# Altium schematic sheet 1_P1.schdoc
size 429 x 518 mm; Symbol: Sheet-Symbol_A4; Device: Sheet-Symbol_A4; Company: 嘉立创EDA; Drawed: Solituder; Version: V8.0; Page Size: A4; @Project Name: FOC12; @Page Count: 1; @Update Date: 2025-05-16; @Create Date: 2024-12-24; @Schematic Name: Schematic1; @Page No: 1; @Page Name: P1; @Board Name: 驱动板; @Create Time: 09:30:22; @Update Time: 20:05:17; Width: 1655; Height: 2000; Region Start: 1; X Region Count: 6; Y Region Count: 4; Blade Width: 10; Title Block Position: 3
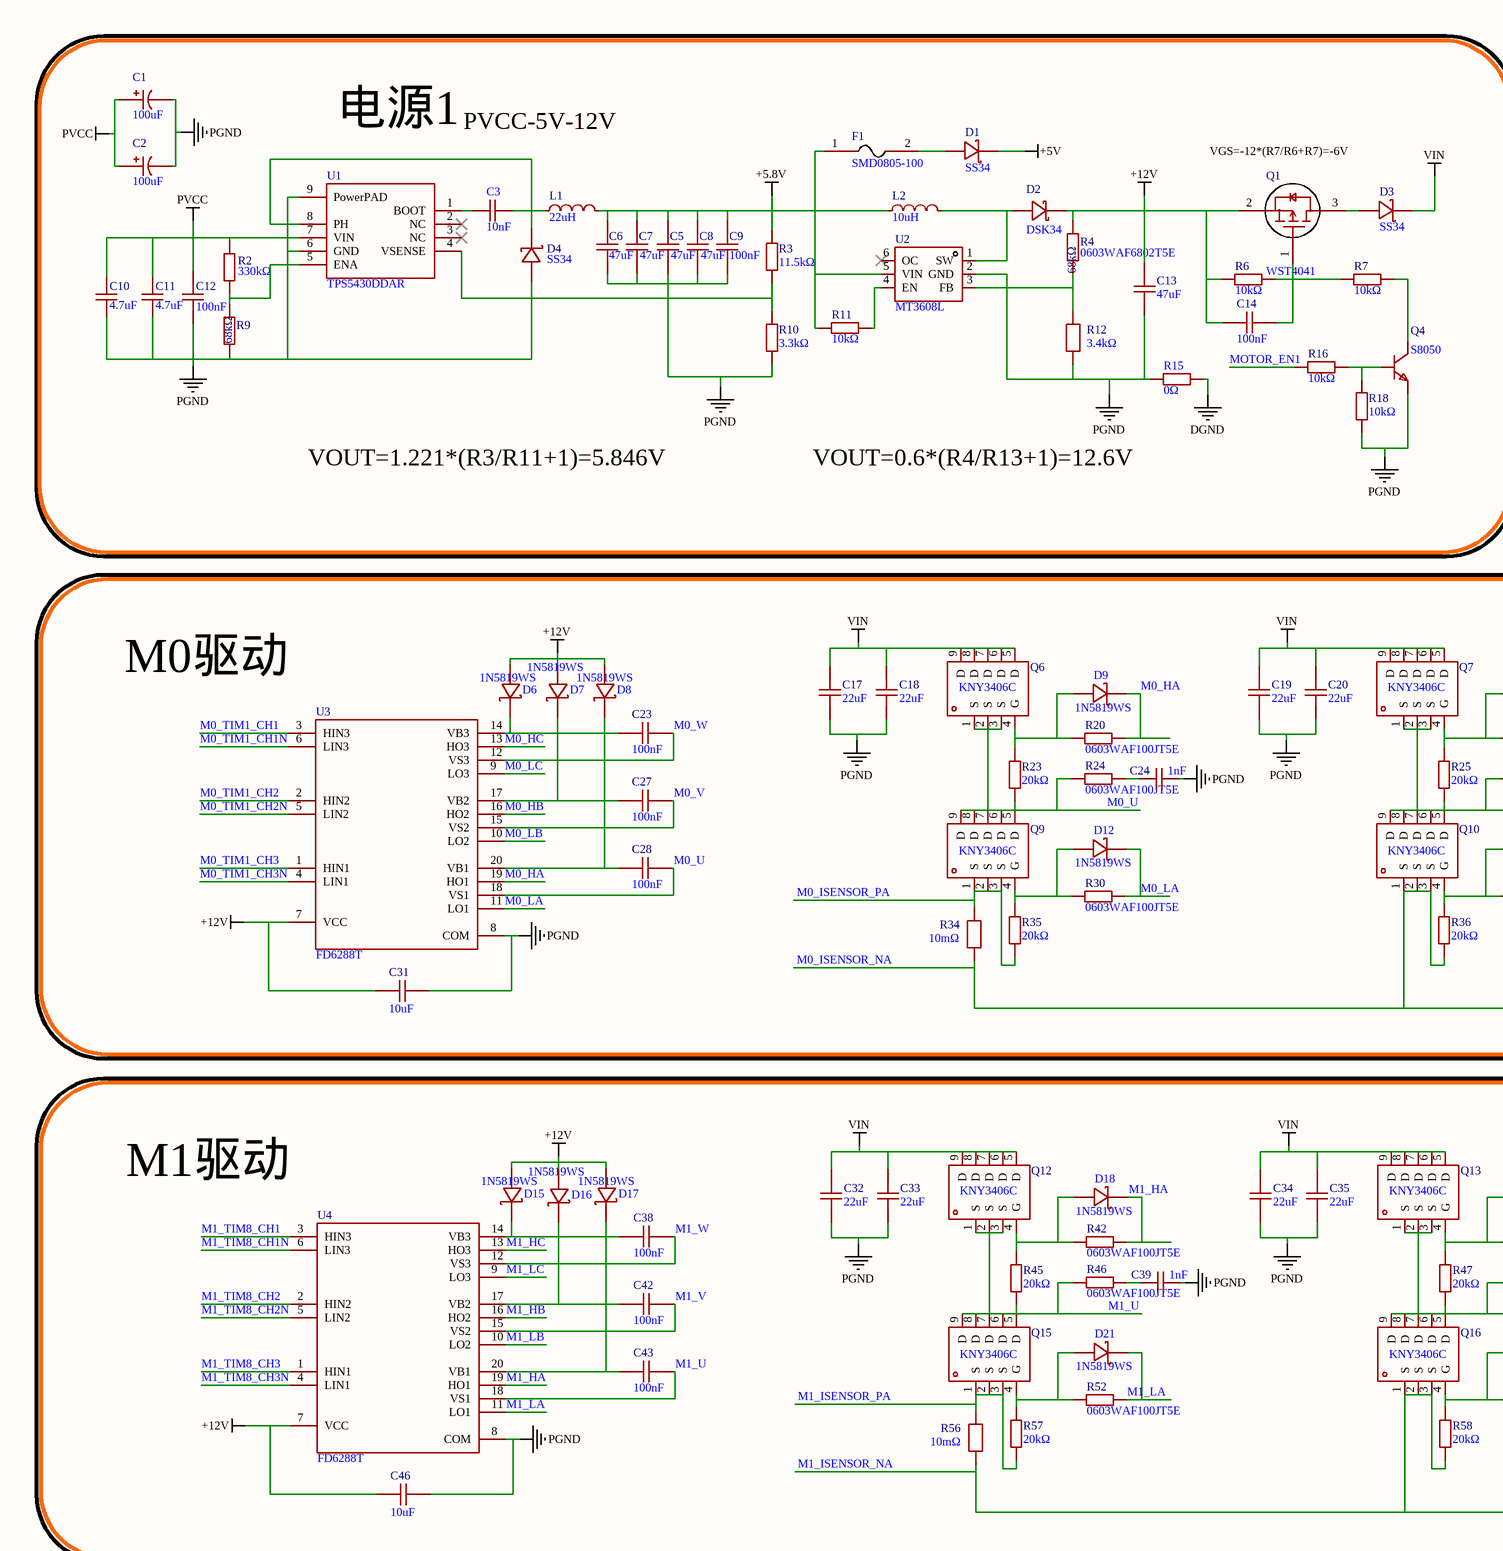
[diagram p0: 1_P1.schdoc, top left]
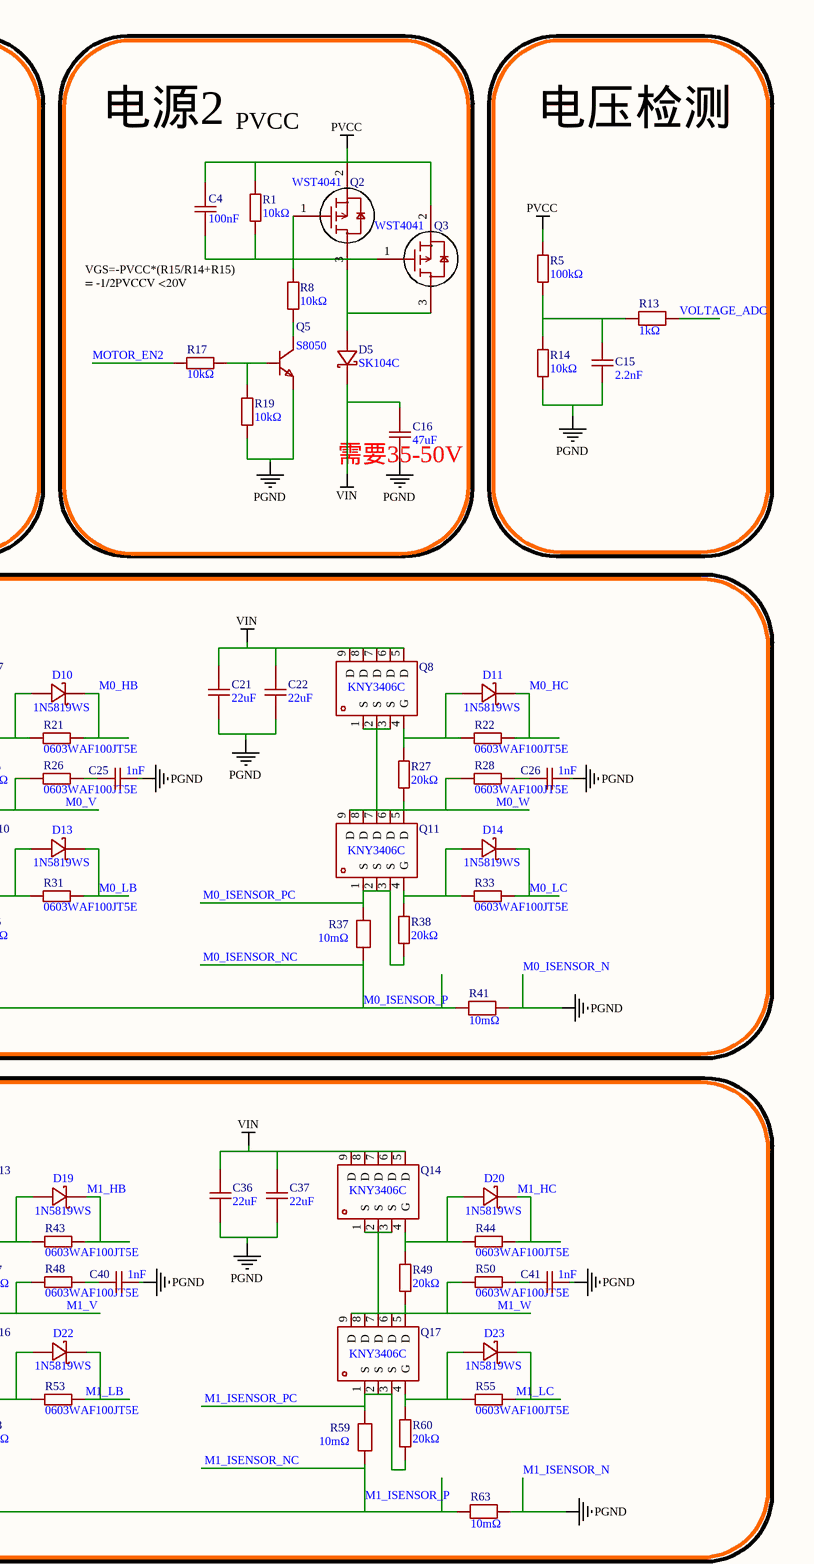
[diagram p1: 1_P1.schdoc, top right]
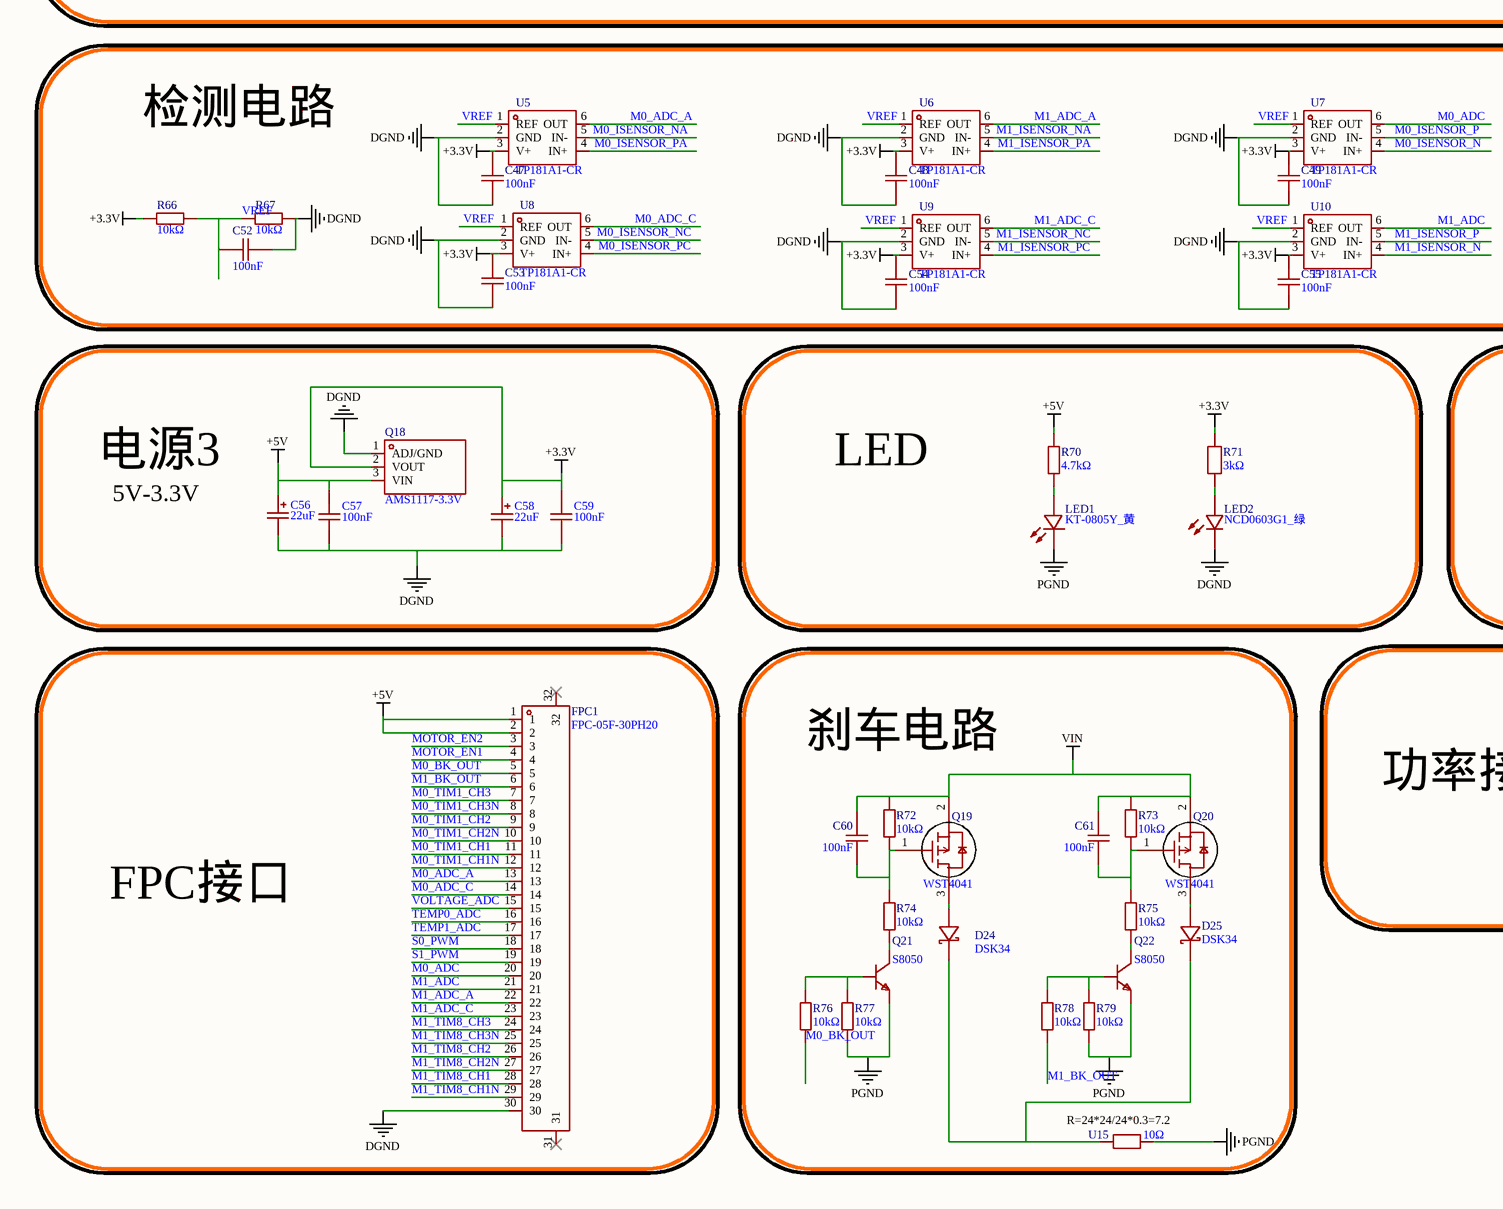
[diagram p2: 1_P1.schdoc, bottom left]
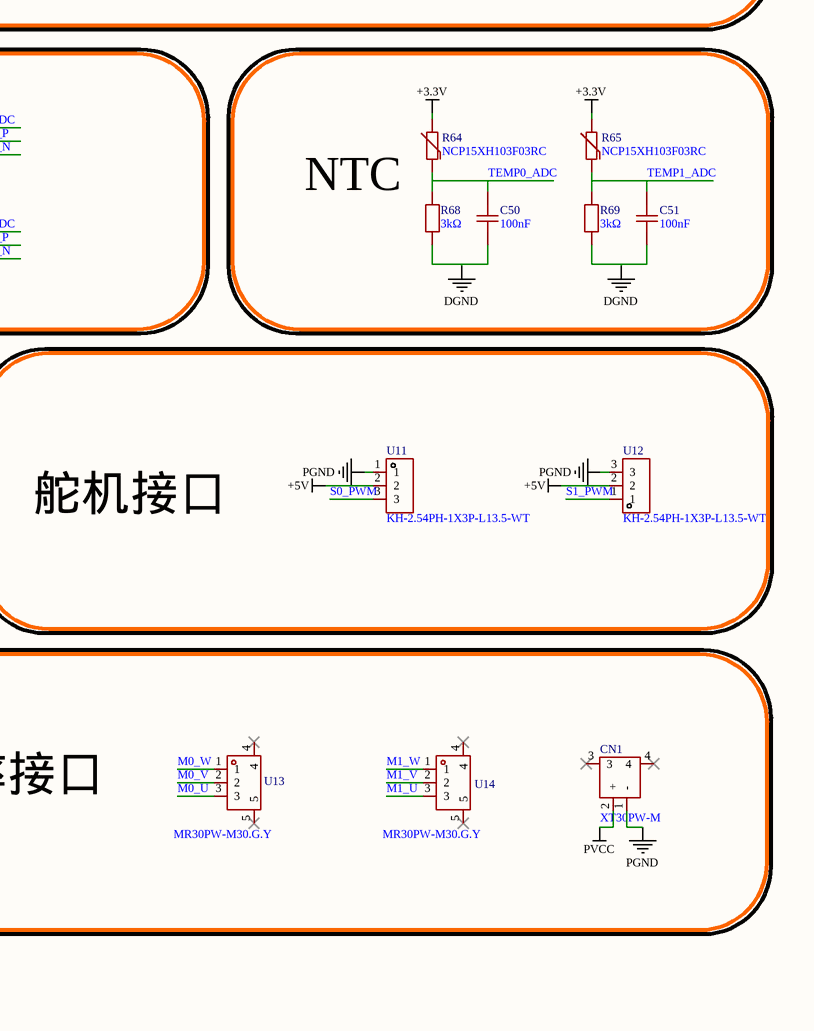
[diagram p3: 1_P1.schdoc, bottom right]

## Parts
C1  100uF  [CAP-SMD_BD10.0-L10.3-W10.3-FD]
C2  100uF  [CAP-SMD_BD10.0-L10.3-W10.3-FD]
C3  10nF  [C0603]
C4  100nF  [C0603]
C5  47uF  [C1206]
C6  47uF  [C1206]
C7  47uF  [C1206]
C8  47uF  [C1206]
C9  100nF  [C0603]
C10  4.7uF  [C0805]
C11  4.7uF  [C0805]
C12  100nF  [C0603]
C13  47uF  [C1206]
C14  100nF  [C0603]
C15  2.2nF  [C0402]
C16  47uF  [C1206]
C17  22uF  [C1206]
C18  22uF  [C1206]
C19  22uF  [C1206]
C20  22uF  [C1206]
C21  22uF  [C1206]
C22  22uF  [C1206]
C23  100nF  [C0603]
C24  1nF  [C0402]
C25  1nF  [C0402]
C26  1nF  [C0402]
C27  100nF  [C0603]
C28  100nF  [C0603]
C31  10uF  [C0805]
C32  22uF  [C1206]
C33  22uF  [C1206]
C34  22uF  [C1206]
C35  22uF  [C1206]
C36  22uF  [C1206]
C37  22uF  [C1206]
C38  100nF  [C0603]
C39  1nF  [C0402]
C40  1nF  [C0402]
C41  1nF  [C0402]
C42  100nF  [C0603]
C43  100nF  [C0603]
C46  10uF  [C0805]
C47  100nF  [C0402]
C48  100nF  [C0402]
C49  100nF  [C0402]
C50  100nF  [C0603]
C51  100nF  [C0603]
C52  100nF  [C0402]
C53  100nF  [C0402]
C54  100nF  [C0402]
C55  100nF  [C0402]
C56  22uF  [CASE-A_3216]
C57  100nF  [C0603]
C58  22uF  [CASE-A_3216]
C59  100nF  [C0603]
C60  100nF  [C0603]
C61  100nF  [C0603]
CN1  XT30PW-M  [CONN-TH_XT30PW-M]
D1  SS34  [SMA_L4.3-W2.6-LS5.2-RD]
D2  DSK34  [SOD-123FL_L2.7-W1.8-LS3.8-RD]
D3  SS34  [SMA_L4.3-W2.6-LS5.2-RD]
D4  SS34  [SMA_L4.3-W2.6-LS5.2-RD]
D5  SK104C  [SMC_L6.9-W5.9-LS7.9-RD]
D6  1N5819WS  [SOD-323_L1.8-W1.3-LS2.5-RD]
D7  1N5819WS  [SOD-323_L1.8-W1.3-LS2.5-RD]
D8  1N5819WS  [SOD-323_L1.8-W1.3-LS2.5-RD]
D9  1N5819WS  [SOD-323_L1.8-W1.3-LS2.5-RD]
D10  1N5819WS  [SOD-323_L1.8-W1.3-LS2.5-RD]
D11  1N5819WS  [SOD-323_L1.8-W1.3-LS2.5-RD]
D12  1N5819WS  [SOD-323_L1.8-W1.3-LS2.5-RD]
D13  1N5819WS  [SOD-323_L1.8-W1.3-LS2.5-RD]
D14  1N5819WS  [SOD-323_L1.8-W1.3-LS2.5-RD]
D15  1N5819WS  [SOD-323_L1.8-W1.3-LS2.5-RD]
D16  1N5819WS  [SOD-323_L1.8-W1.3-LS2.5-RD]
D17  1N5819WS  [SOD-323_L1.8-W1.3-LS2.5-RD]
D18  1N5819WS  [SOD-323_L1.8-W1.3-LS2.5-RD]
D19  1N5819WS  [SOD-323_L1.8-W1.3-LS2.5-RD]
D20  1N5819WS  [SOD-323_L1.8-W1.3-LS2.5-RD]
D21  1N5819WS  [SOD-323_L1.8-W1.3-LS2.5-RD]
D22  1N5819WS  [SOD-323_L1.8-W1.3-LS2.5-RD]
D23  1N5819WS  [SOD-323_L1.8-W1.3-LS2.5-RD]
D24  DSK34  [SOD-123FL_L2.7-W1.8-LS3.8-RD]
D25  DSK34  [SOD-123FL_L2.7-W1.8-LS3.8-RD]
F1  SMD0805-100  [F0805]
FPC1  FPC-05F-30PH20  [FPC-SMD_30P-P0.50_XUNPU_FPC-05F-30PH20]
L1  22uH  [IND-SMD_L7.3-W6.6_MHCI06030]
L2  10uH  [IND-SMD_L5.4-W5.2_FXL0530]
LED1  KT-0805Y_黄  [LED0805-R-RD]
LED2  NCD0603G1_绿  [LED0603-RD_1]
Q1  WST4041  [SOT-23_L2.9-W1.3-P1.90-LS2.4-BR]
Q2  WST4041  [SOT-23_L2.9-W1.3-P1.90-LS2.4-BR]
Q3  WST4041  [SOT-23_L2.9-W1.3-P1.90-LS2.4-BR]
Q4  S8050  [SOT-23-3_L2.9-W1.3-P1.90-LS2.4-BR]
Q5  S8050  [SOT-23-3_L2.9-W1.3-P1.90-LS2.4-BR]
Q6  KNY3406C  [PDFN-8_L4.9-W5.8-P1.27-LS6.1-BL]
Q7  KNY3406C  [PDFN-8_L4.9-W5.8-P1.27-LS6.1-BL]
Q8  KNY3406C  [PDFN-8_L4.9-W5.8-P1.27-LS6.1-BL]
Q9  KNY3406C  [PDFN-8_L4.9-W5.8-P1.27-LS6.1-BL]
Q10  KNY3406C  [PDFN-8_L4.9-W5.8-P1.27-LS6.1-BL]
Q11  KNY3406C  [PDFN-8_L4.9-W5.8-P1.27-LS6.1-BL]
Q12  KNY3406C  [PDFN-8_L4.9-W5.8-P1.27-LS6.1-BL]
Q13  KNY3406C  [PDFN-8_L4.9-W5.8-P1.27-LS6.1-BL]
Q14  KNY3406C  [PDFN-8_L4.9-W5.8-P1.27-LS6.1-BL]
Q15  KNY3406C  [PDFN-8_L4.9-W5.8-P1.27-LS6.1-BL]
Q16  KNY3406C  [PDFN-8_L4.9-W5.8-P1.27-LS6.1-BL]
Q17  KNY3406C  [PDFN-8_L4.9-W5.8-P1.27-LS6.1-BL]
Q18  AMS1117-3.3V  [SOT-89-3_L4.5-W2.5-P1.50-LS4.2-BR]
Q19  WST4041  [SOT-23_L2.9-W1.3-P1.90-LS2.4-BR]
Q20  WST4041  [SOT-23_L2.9-W1.3-P1.90-LS2.4-BR]
Q21  S8050  [SOT-23-3_L2.9-W1.3-P1.90-LS2.4-BR]
Q22  S8050  [SOT-23-3_L2.9-W1.3-P1.90-LS2.4-BR]
R1  10kΩ  [R0402]
R2  330kΩ  [R0603]
R3  11.5kΩ  [R0402]
R4  0603WAF6802T5E  value 68kΩ  [R0603]
R5  100kΩ  [R0402]
R6  10kΩ  [R0402]
R7  10kΩ  [R0402]
R8  10kΩ  [R0402]
R9  value 68kΩ  [R0603]  (hidden comment: 0603WAF6802T5E)
R10  3.3kΩ  [R0402]
R11  10kΩ  [R0402]
R12  3.4kΩ  [R0603]
R13  1kΩ  [R0402]
R14  10kΩ  [R0402]
R15  0Ω  [R0603]
R16  10kΩ  [R0402]
R17  10kΩ  [R0402]
R18  10kΩ  [R0402]
R19  10kΩ  [R0402]
R20  0603WAF100JT5E  [R0603]
R21  0603WAF100JT5E  [R0603]
R22  0603WAF100JT5E  [R0603]
R23  20kΩ  [R0402]
R24  0603WAF100JT5E  [R0603]
R25  20kΩ  [R0402]
R26  0603WAF100JT5E  [R0603]
R27  20kΩ  [R0402]
R28  0603WAF100JT5E  [R0603]
R30  0603WAF100JT5E  [R0603]
R31  0603WAF100JT5E  [R0603]
R33  0603WAF100JT5E  [R0603]
R34  10mΩ  [R2512]
R35  20kΩ  [R0402]
R36  20kΩ  [R0402]
R37  10mΩ  [R2512]
R38  20kΩ  [R0402]
R41  10mΩ  [R2512]
R42  0603WAF100JT5E  [R0603]
R43  0603WAF100JT5E  [R0603]
R44  0603WAF100JT5E  [R0603]
R45  20kΩ  [R0402]
R46  0603WAF100JT5E  [R0603]
R47  20kΩ  [R0402]
R48  0603WAF100JT5E  [R0603]
R49  20kΩ  [R0402]
R50  0603WAF100JT5E  [R0603]
R52  0603WAF100JT5E  [R0603]
R53  0603WAF100JT5E  [R0603]
R55  0603WAF100JT5E  [R0603]
R56  10mΩ  [R2512]
R57  20kΩ  [R0402]
R58  20kΩ  [R0402]
R59  10mΩ  [R2512]
R60  20kΩ  [R0402]
R63  10mΩ  [R2512]
R64  NCP15XH103F03RC  [R0402]
R65  NCP15XH103F03RC  [R0402]
R66  10kΩ  [R0402]
R67  10kΩ  [R0402]
R68  3kΩ  [R0402]
R69  3kΩ  [R0402]
R70  4.7kΩ  [R0402]
R71  3kΩ  [R0402]
R72  10kΩ  [R0402]
R73  10kΩ  [R0402]
R74  10kΩ  [R0402]
R75  10kΩ  [R0402]
R76  10kΩ  [R0402]
R77  10kΩ  [R0402]
R78  10kΩ  [R0402]
R79  10kΩ  [R0402]
U1  TPS5430DDAR  [ESOP-8_L4.9-W3.9-P1.27-LS6.0-TL-EP]
U2  MT3608L  [SOT-23-6_L2.9-W1.6-P0.95-LS2.8-BL_3]
U3  FD6288T  [TSSOP-20_L6.5-W4.4-P0.65-LS6.4-BL]
U4  FD6288T  [TSSOP-20_L6.5-W4.4-P0.65-LS6.4-BL]
U5  TP181A1-CR  [SC70-6_L2.1-W1.3-P0.65-LS2.3-BL]
U6  TP181A1-CR  [SC70-6_L2.1-W1.3-P0.65-LS2.3-BL]
U7  TP181A1-CR  [SC70-6_L2.1-W1.3-P0.65-LS2.3-BL]
U8  TP181A1-CR  [SC70-6_L2.1-W1.3-P0.65-LS2.3-BL]
U9  TP181A1-CR  [SC70-6_L2.1-W1.3-P0.65-LS2.3-BL]
U10  TP181A1-CR  [SC70-6_L2.1-W1.3-P0.65-LS2.3-BL]
U11  KH-2.54PH-1X3P-L13.5-WT  [HDR-SMD_3P-P2.54-H-M_KH-2.54PH-1X3P-L13.5-WT]
U12  KH-2.54PH-1X3P-L13.5-WT  [HDR-SMD_3P-P2.54-H-M_KH-2.54PH-1X3P-L13.5-WT]
U13  MR30PW-M30.G.Y  [CONN-TH_MR30PW-M30-G-Y]
U14  MR30PW-M30.G.Y  [CONN-TH_MR30PW-M30-G-Y]
U15  10Ω  [TO-220-2_L10.1-W4.5-P5.08-L]

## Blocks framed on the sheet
电源1: C1-C3 C5-C14 D1-D4 F1 L1 L2 Q1 Q4 R2-R4 R6 R7 R9-R12 R15 R16 R18 U1 U2
电源2: C4 C16 D5 Q2 Q3 Q5 R1 R8 R17 R19
电压检测: C15 R5 R13 R14
M0驱动: C17-C28 C31 D6-D14 Q6-Q11 R20-R28 R30 R31 R33-R38 R41 U3
M1驱动: C32-C43 C46 D15-D23 Q12-Q17 R42-R50 R52 R53 R55-R60 R63 U4
检测电路: C47-C49 C52-C55 R66 R67 U5-U10
NTC: C50 C51 R64 R65 R68 R69
电源3: C56-C59 Q18
LED: LED1 LED2 R70 R71
舵机接口: U11 U12
FPC接口: FPC1
刹车电路: C60 C61 D24 D25 Q19-Q22 R72-R79 U15
功率接口: CN1 U13 U14

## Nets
+3.3V: C47.2 C48.2 C49.2 C53.2 C54.2 C55.2 C58.1 C59.2 Q18.2(VOUT) R64.2 R65.2 R66.1 R71.2 U5.3(V+) U6.3(V+) U7.3(V+) U8.3(V+) U9.3(V+) U10.3(V+)
+5.8V: C5.2 C6.2 C7.2 C8.2 C9.1 F1.1 L1.2 L2.1 R3.2 R11.2 U2.5(VIN)
+5V: C56.1 C57.2 D1.1(K) FPC1.1 FPC1.2 Q18.3(VIN) R70.2 U11.2 U12.2
+12V: C13.2 C14.2 C31.2 C46.2 D2.1(K) D6.2(A) D7.2(A) D8.2(A) D15.2(A) D16.2(A) D17.2(A) Q1.2(S) R4.2 R6.2 U3.7(VCC) U4.7(VCC)
DGND: C47.1 C48.1 C49.1 C50.1 C51.1 C52.1 C53.1 C54.1 C55.1 C56.2 C57.1 C58.2 C59.1 FPC1.30 LED2.1(K) Q18.1(ADJ/GND) R15.1 R67.2 R68.1 R69.1 U5.2(GND) U6.2(GND) U7.2(GND) U8.2(GND) U9.2(GND) U10.2(GND)
M0_ISENSOR_N: C1.2 C2.2 C5.1 C6.1 C7.1 C8.1 C9.2 C10.1 C11.1 C12.1 C13.1 C15.1 C16.1 C17.1 C18.1 C19.1 C20.1 C21.1 C22.1 C24.2 C25.2 C26.2 C31.1 C32.1 C33.1 C34.1 C35.1 C36.1 C37.1 C39.2 C40.2 C41.2 C46.1 CN1.1(-) D4.2(A) LED1.2(-) Q4.2(E) Q5.2(E) Q21.2(E) Q22.2(E) R9.1 R10.1 R12.1 R14.2 R15.2 R18.2 R19.2 R41.1 R63.1 R77.2 R79.2 U1.6(GND) U1.9(PowerPAD) U2.2(GND) U3.8(COM) U4.8(COM) U7.4(IN+) U10.4(IN+) U11.1 U12.3 U15.2  [also labelled M1_ISENSOR_N, PGND]
PVCC: C1.1 C2.1 C4.2 C10.2 C11.2 C12.2 CN1.2(+) Q2.2(S) Q3.2(S) R1.2 R2.2 R5.2 U1.7(VIN)
VIN: C16.2 C17.2 C18.2 C19.2 C20.2 C21.2 C22.2 C32.2 C33.2 C34.2 C35.2 C36.2 C37.2 C60.2 C61.2 D3.1(K) D5.1(K) Q6.5(D) Q6.6(D) Q6.7(D) Q6.8(D) Q6.9(D) Q7.5(D) Q7.6(D) Q7.7(D) Q7.8(D) Q7.9(D) Q8.5(D) Q8.6(D) Q8.7(D) Q8.8(D) Q8.9(D) Q12.5(D) Q12.6(D) Q12.7(D) Q12.8(D) Q12.9(D) Q13.5(D) Q13.6(D) Q13.7(D) Q13.8(D) Q13.9(D) Q14.5(D) Q14.6(D) Q14.7(D) Q14.8(D) Q14.9(D) Q19.2(S) Q20.2(S) R72.2 R73.2
M0_ADC: FPC1.20 U7.6(OUT)
M0_ADC_A: FPC1.13 U5.6(OUT)
M0_ADC_C: FPC1.14 U8.6(OUT)
M0_BK_OUT: FPC1.5 R76.2
M0_HA: D9.1(K) R20.1 U3.19(HO1)
M0_HB: D10.1(K) R21.1 U3.16(HO2)
M0_HC: D11.1(K) R22.1 U3.13(HO3)
M0_ISENSOR_NA: Q10.1(S) Q10.2(S) Q10.3(S) R34.1 R36.1 R37.1 R41.2 U5.5(IN-) U7.5(IN-) U8.5(IN-)  [also labelled M0_ISENSOR_NC, M0_ISENSOR_P]
M0_ISENSOR_PA: Q9.1(S) Q9.2(S) Q9.3(S) R34.2 R35.1 U5.4(IN+)
M0_ISENSOR_PC: Q11.1(S) Q11.2(S) Q11.3(S) R37.2 R38.1 U8.4(IN+)
M0_LA: D12.1(K) R30.1 U3.11(LO1)
M0_LB: D13.1(K) R31.1 U3.10(LO2)
M0_LC: D14.1(K) R33.1 U3.9(LO3)
M0_TIM1_CH1: FPC1.11 U3.3(HIN3)
M0_TIM1_CH1N: FPC1.12 U3.6(LIN3)
M0_TIM1_CH2: FPC1.9 U3.2(HIN2)
M0_TIM1_CH2N: FPC1.10 U3.5(LIN2)
M0_TIM1_CH3: FPC1.7 U3.1(HIN1)
M0_TIM1_CH3N: FPC1.8 U3.4(LIN1)
M0_U: C28.2 Q6.1(S) Q6.2(S) Q6.3(S) Q9.5(D) Q9.6(D) Q9.7(D) Q9.8(D) Q9.9(D) R23.1 R24.2 U3.18(VS1) U13.3
M0_V: C27.2 Q7.1(S) Q7.2(S) Q7.3(S) Q10.5(D) Q10.6(D) Q10.7(D) Q10.8(D) Q10.9(D) R25.1 R26.2 U3.15(VS2) U13.2
M0_W: C23.2 Q8.1(S) Q8.2(S) Q8.3(S) Q11.5(D) Q11.6(D) Q11.7(D) Q11.8(D) Q11.9(D) R27.1 R28.2 U3.12(VS3) U13.1
M1_ADC: FPC1.21 U10.6(OUT)
M1_ADC_A: FPC1.22 U6.6(OUT)
M1_ADC_C: FPC1.23 U9.6(OUT)
M1_BK_OUT: FPC1.6 R78.2
M1_HA: D18.1(K) R42.1 U4.19(HO1)
M1_HB: D19.1(K) R43.1 U4.16(HO2)
M1_HC: D20.1(K) R44.1 U4.13(HO3)
M1_ISENSOR_NA: Q16.1(S) Q16.2(S) Q16.3(S) R56.1 R58.1 R59.1 R63.2 U6.5(IN-) U9.5(IN-) U10.5(IN-)  [also labelled M1_ISENSOR_NC, M1_ISENSOR_P]
M1_ISENSOR_PA: Q15.1(S) Q15.2(S) Q15.3(S) R56.2 R57.1 U6.4(IN+)
M1_ISENSOR_PC: Q17.1(S) Q17.2(S) Q17.3(S) R59.2 R60.1 U9.4(IN+)
M1_LA: D21.1(K) R52.1 U4.11(LO1)
M1_LB: D22.1(K) R53.1 U4.10(LO2)
M1_LC: D23.1(K) R55.1 U4.9(LO3)
M1_TIM8_CH1: FPC1.28 U4.3(HIN3)
M1_TIM8_CH1N: FPC1.29 U4.6(LIN3)
M1_TIM8_CH2: FPC1.26 U4.2(HIN2)
M1_TIM8_CH2N: FPC1.27 U4.5(LIN2)
M1_TIM8_CH3: FPC1.24 U4.1(HIN1)
M1_TIM8_CH3N: FPC1.25 U4.4(LIN1)
M1_U: C43.2 Q12.1(S) Q12.2(S) Q12.3(S) Q15.5(D) Q15.6(D) Q15.7(D) Q15.8(D) Q15.9(D) R45.1 R46.2 U4.18(VS1) U14.3
M1_V: C42.2 Q13.1(S) Q13.2(S) Q13.3(S) Q16.5(D) Q16.6(D) Q16.7(D) Q16.8(D) Q16.9(D) R47.1 R48.2 U4.15(VS2) U14.2
M1_W: C38.2 Q14.1(S) Q14.2(S) Q14.3(S) Q17.5(D) Q17.6(D) Q17.7(D) Q17.8(D) Q17.9(D) R49.1 R50.2 U4.12(VS3) U14.1
MOTOR_EN1: FPC1.4 R16.2
MOTOR_EN2: FPC1.3 R17.2
S0_PWM: FPC1.18 U11.3
S1_PWM: FPC1.19 U12.1
TEMP0_ADC: C50.2 FPC1.16 R64.1 R68.2
TEMP1_ADC: C51.2 FPC1.17 R65.1 R69.2
VOLTAGE_ADC: FPC1.15 R13.1
VREF: C52.2 R66.2 R67.1 U5.1(REF) U6.1(REF) U7.1(REF) U8.1(REF) U9.1(REF) U10.1(REF)
NetC3_1: C3.1 U1.1(BOOT)
NetC3_2: C3.2 D4.1(K) L1.1 U1.8(PH)
NetC4_1: C4.1 Q2.1(G) Q3.1(G) R1.1 R8.2
NetC14_1: C14.1 Q1.1(G) R6.1 R7.2
NetC15_2: C15.2 R5.1 R13.2 R14.1
NetC23_1: C23.1 D6.1(K) U3.14(VB3)
NetC24_1: C24.1 R24.1
NetC25_1: C25.1 R26.1
NetC26_1: C26.1 R28.1
NetC27_1: C27.1 D7.1(K) U3.17(VB2)
NetC28_1: C28.1 D8.1(K) U3.20(VB1)
NetC38_1: C38.1 D15.1(K) U4.14(VB3)
NetC39_1: C39.1 R46.1
NetC40_1: C40.1 R48.1
NetC41_1: C41.1 R50.1
NetC42_1: C42.1 D16.1(K) U4.17(VB2)
NetC43_1: C43.1 D17.1(K) U4.20(VB1)
NetC60_1: C60.1 Q19.1(G) R72.1 R74.2
NetC61_1: C61.1 Q20.1(G) R73.1 R75.2
NetD1_2: D1.2(A) F1.2
NetD2_2: D2.2(A) L2.2 U2.1(SW)
NetD3_2: D3.2(A) Q1.3(D)
NetD5_2: D5.2(A) Q2.3(D) Q3.3(D)
NetD9_2: D9.2(A) Q6.4(G) R20.2 R23.2
NetD10_2: D10.2(A) Q7.4(G) R21.2 R25.2
NetD11_2: D11.2(A) Q8.4(G) R22.2 R27.2
NetD12_2: D12.2(A) Q9.4(G) R30.2 R35.2
NetD13_2: D13.2(A) Q10.4(G) R31.2 R36.2
NetD14_2: D14.2(A) Q11.4(G) R33.2 R38.2
NetD18_2: D18.2(A) Q12.4(G) R42.2 R45.2
NetD19_2: D19.2(A) Q13.4(G) R43.2 R47.2
NetD20_2: D20.2(A) Q14.4(G) R44.2 R49.2
NetD21_2: D21.2(A) Q15.4(G) R52.2 R57.2
NetD22_2: D22.2(A) Q16.4(G) R53.2 R58.2
NetD23_2: D23.2(A) Q17.4(G) R55.2 R60.2
NetD24_1: D24.1(K) D25.1(K) U15.1
NetD24_2: D24.2(A) Q19.3(D)
NetD25_2: D25.2(A) Q20.3(D)
NetLED1_1: LED1.1(+) R70.1
NetLED2_2: LED2.2(A) R71.1
NetQ4_1: Q4.1(B) R16.1 R18.1
NetQ4_3: Q4.3(C) R7.1
NetQ5_1: Q5.1(B) R17.1 R19.1
NetQ5_3: Q5.3(C) R8.1
NetQ21_1: Q21.1(B) R76.1 R77.1
NetQ21_3: Q21.3(C) R74.1
NetQ22_1: Q22.1(B) R78.1 R79.1
NetQ22_3: Q22.3(C) R75.1
NetR2_1: R2.1 R9.2 U1.5(ENA)
NetR3_1: R3.1 R10.2 U1.4(VSENSE)
NetR4_1: R4.1 R12.2 U2.3(FB)
NetR11_1: R11.1 U2.4(EN)

Not connected (* = marked no-connect by the designer): CN1 3* 4*; FPC1 31* 32*; U1 2(NC)* 3(NC)*; U2 6(OC)*; U13 4* 5*; U14 4* 5*

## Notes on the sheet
- PVCC-5V-12V
- PVCC
- VGS=-12*(R7/R6+R7)=-6V
- (near R17) VGS=-PVCC*(R15/R14+R15)
  =-1/2PVCCV<20V
- VOUT=1.221*(R3/R11+1)=5.846V
- VOUT=0.6*(R4/R13+1)=12.6V
- (near C16) 需要35-50V
- 5V-3.3V
- (near U15) R=24*24/24*0.3=7.2

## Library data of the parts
C1 C2 = VMME0841J101MV: Manufacturer: Ymin(永铭); Add into BOM: yes; Tolerance: ±20%; Rated Voltage: 63V
C3 = CC0603JRX7R9BB103: Manufacturer: YAGEO(国巨); Add into BOM: yes; Tolerance: ±5%; Voltage Rated: 50V; Temperature Coefficient: X7R
C4 C9 C12 C14 C23 C27 C28 C38 C42 C43 C50 C51 C57 C59-C61 = CC0603KRX7R9BB104: Manufacturer: YAGEO(国巨); Add into BOM: yes; Tolerance: ±10%; Voltage Rated: 50V; Temperature Coefficient: X7R
C5-C8 C16 = HGC1206R5476M100NSPJ: Manufacturer: Chinocera(华瓷); Add into BOM: yes; Tolerance: ±20%; Voltage Rated: 10V; Temperature Coefficient: X5R
C10 C11 = CL21A475KBQNNNE: Manufacturer: SAMSUNG(三星); Add into BOM: yes; Tolerance: ±10%; Voltage Rated: 50V; Temperature Coefficient: X5R
C13 = HGC1206R5476M250NSPJ: Manufacturer: Chinocera(华瓷); Add into BOM: yes; Tolerance: ±20%; Voltage Rated: 25V; Temperature Coefficient: X5R
C15 = 0402B222K500NT: Manufacturer: FH(风华); Add into BOM: yes; Tolerance: ±10%; Voltage Rated: 50V; Temperature Coefficient: X7R
C17-C22 C32-C37 = CGA1206X5R226M350NT: Manufacturer: HRE(芯声); Add into BOM: yes; Tolerance: ±20%; Voltage Rated: 35V; Temperature Coefficient: X5R
C24-C26 C39-C41 = CC0402KRX7R9BB102: Manufacturer: YAGEO(国巨); Add into BOM: yes; Tolerance: ±10%; Voltage Rated: 50V; Temperature Coefficient: X7R
C31 C46 = HGC0805R5106K500NSLJ: Manufacturer: Chinocera(华瓷); Add into BOM: yes; Tolerance: ±10%; Voltage Rated: 50V; Temperature Coefficient: X5R
C47-C49 C52-C55 = CL05B104KO5NNNC: Manufacturer: SAMSUNG(三星); Add into BOM: yes; Tolerance: ±10%; Voltage Rated: 16V; Temperature Coefficient: X7R
C56 C58 = TAJA226K010RNJ: Manufacturer: Kyocera AVX; Add into BOM: yes; Tolerance: ±10%; Rated Voltage: 10V; Equivalent Series Resistance(ESR): 3Ω@100kHz
CN1 = XT30PW-M: Manufacturer: AMASS(艾迈斯); Add into BOM: yes
D1 D3 D4 = SS34_C8678: Manufacturer: MDD(辰达半导体); Add into BOM: yes; Diode Configuration: 独立式; Forward Voltage (Vf@If): 550mV@3A; Reverse Voltage (Vr): 40V; Rectified Current: 3A; Reverse Leakage Current (Ir): 500uA@40V
D2 D24 D25 = DSK34_C7502709: Manufacturer: 宏迦橙; Add into BOM: yes; Diode Configuration: 独立式; Forward Voltage (Vf@If): 550mV@3A; Reverse Voltage (Vr): 40V; Rectified Current: 3A; Reverse Leakage Current (Ir): 500uA
D5 = SK104C_C18199211: Manufacturer: 宏迦橙; Add into BOM: yes; Diode Configuration: 独立式; Forward Voltage (Vf@If): 550mV@10A; Reverse Voltage (Vr): 40V; Rectified Current: 10A; Reverse Leakage Current (Ir): 500uA@40V
D6-D23 = 1N5819WS_C191023: Manufacturer: Hottech(合科泰); Add into BOM: yes; Reverse Voltage (Vr): 40V; Average Rectified Current (Io): 1A; Forward Voltage (Vf@If): 600mV@1A
F1 = SMD0805-100: Manufacturer: 台湾陆海; Add into BOM: yes; Operating Voltage (Max): 6V; Current Rating (Max): 100A; Hold Current: 1A; Trip Current: 1.95A
FPC1 = FPC-05F-30PH20: Manufacturer: XUNPU(讯普); Add into BOM: yes; Locking Feature: 翻盖式; Number of Contacts: 30P; Pitch: 0.5mm; FFC, FCB Thickness: 0.3mm
L1 = SMMS0630-220M: Manufacturer: SXN(顺翔诺); Add into BOM: yes; Tolerance: ±20%
L2 = FXL0530-100-M: Manufacturer: cjiang(长江微电); Add into BOM: yes; Tolerance: ±20%; Rated Current: 3.2A; Saturation Current (Isat): 3.5A; DC Resistance (DCR): 110mΩ
LED1 = KT-0805Y: Manufacturer: KENTO; Symbol: 17-21SUYC/TR8; Add into BOM: yes; Emitted Color: 黄色
LED2 = NCD0603G1: Manufacturer: 国星光电; Symbol: FC-D1608UGK-520D10; Add into BOM: yes; Emitted Color: 翠绿色; Forward Voltage (VF): 2.6V~3.6V; Power Dissipation: 72mW; Forward Current: 10mA; Dominant Wavelength: 515nm~530nm; Lens Color: 无色透明透镜; Luminous Intensity: 330mcd~900mcd; Viewing Angle: 130°
Q1-Q3 Q19 Q20 = WST4041: Manufacturer: WINSOK(微硕); Add into BOM: yes; Type: 1个P沟道; Drain Source Voltage (Vdss): 40V; Continuous Drain Current (Id): 6A; Power Dissipation (Pd): 1.4W; Drain Source On Resistance (RDS(on)@Vgs,Id): 40mΩ@10V,3A; Gate Threshold Voltage (Vgs(th)@Id): 2.2V@250uA
Q4 Q5 Q21 Q22 = S8050: Manufacturer: Doeshare(德芯); Symbol: S8050_C2931719; Add into BOM: yes
Q6-Q17 = KNY3406C: Manufacturer: KIA 半导体; Add into BOM: yes; Type: N沟道; Drain Source Voltage (Vdss): 60V; Continuous Drain Current (Id): 80A; Drain Source On Resistance (RDS(on)@Vgs,Id): 8.5mΩ@10V,10A; Power Dissipation (Pd): 41W; Gate Threshold Voltage (Vgs(th)@Id): 2.5V@250μA
Q18 = AMS1117-3.3V_C5120796: Manufacturer: MSKSEMI(美森科); Add into BOM: yes; Output Type: 固定; Maximum Input Voltage: 18V; Output Voltage: 3.3V; MAX Output Current: 1A; Dropout Voltage: 1.4V@(1A); standby current: 12mA; Output Polarity: 正极; Number of Outputs: 1
R1 R6-R8 R11 R14 R16-R19 R66 R67 R72-R79 = 0402WGF1002TCE: Manufacturer: UNI-ROYAL(厚声); Add into BOM: yes; Tolerance: ±1%; Power(Watts): 62.5mW; Overload Voltage (Max): 50V; Temperature Coefficient: ±100ppm/℃
R2 = 0603WAF3303T5E: Manufacturer: UNI-ROYAL(厚声); Add into BOM: yes; Tolerance: ±1%; Power(Watts): 1/10W; Overload Voltage (Max): 75V; Temperature Coefficient: ±100ppm/℃
R3 = 0402WGF1152TCE: Manufacturer: UNI-ROYAL(厚声); Add into BOM: yes; Tolerance: ±1%; Power(Watts): 62.5mW; Overload Voltage (Max): 50V; Temperature Coefficient: ±100ppm/℃
R4 R9 = 0603WAF6802T5E: Manufacturer: UNI-ROYAL(厚声); Add into BOM: yes
R5 = 0402WGF1003TCE: Manufacturer: UNI-ROYAL(厚声); Add into BOM: yes; Tolerance: ±1%; Power(Watts): 1/16W; Overload Voltage (Max): 50V; Temperature Coefficient: ±100ppm/℃
R10 = 0402WGF3301TCE: Manufacturer: UNI-ROYAL(厚声); Add into BOM: yes; Tolerance: ±1%; Power(Watts): 62.5mW; Overload Voltage (Max): 50V; Temperature Coefficient: ±100ppm/℃
R12 = FRC0603F3401TS: Manufacturer: FOJAN(富捷); Add into BOM: yes; Tolerance: ±1%; Power(Watts): 100mW; Overload Voltage (Max): 75V; Temperature Coefficient: ±100ppm/℃
R13 = FRC0402J102 TS: Manufacturer: FOJAN(富捷); Add into BOM: yes; Tolerance: ±5%; Power(Watts): 62.5mW; Overload Voltage (Max): 50V; Temperature Coefficient: ±100ppm/℃
R15 = 0603WAF0000T5E: Manufacturer: UNI-ROYAL(厚声); Add into BOM: yes; Tolerance: ±1%; Power(Watts): 1/10W; Overload Voltage (Max): 75V
R20-R22 R24 R26 R28 R30 R31 R33 R42-R44 R46 R48 R50 R52 R53 R55 = 0603WAF100JT5E: Manufacturer: UNI-ROYAL(厚声); Value: 10Ω; Add into BOM: yes
R23 R25 R27 R35 R36 R38 R45 R47 R49 R57 R58 R60 = 0402WGF2002TCE: Manufacturer: UNI-ROYAL(厚声); Add into BOM: yes; Tolerance: ±1%; Power(Watts): 62.5mW; Overload Voltage (Max): 50V; Temperature Coefficient: ±100ppm/℃
R34 R37 R41 R56 R59 R63 = PA2512FKE7T0R01E: Manufacturer: YAGEO(国巨); Add into BOM: yes; Tolerance: ±1%; Power(Watts): 3W; Temperature Coefficient: ±50ppm/℃
R64 R65 = NCP15XH103F03RC: Manufacturer: muRata(村田); Add into BOM: yes; Resistance @ 25℃: 10kΩ; B Constant (25℃/50℃): 3380K; Resistance Tolerance: ±1%; B Constant (25℃/85℃): 3434K; B Constant (25℃/100℃): 3455K; Power: 100mW; Steady State Current (Max): 310uA
R68 R69 R71 = FRC0402F3001TS: Manufacturer: FOJAN(富捷); Add into BOM: yes; Tolerance: ±1%; Power(Watts): 62.5mW; Overload Voltage (Max): 50V; Temperature Coefficient: ±100ppm/℃
R70 = 0402WGF4701TCE: Manufacturer: UNI-ROYAL(厚声); Add into BOM: yes; Tolerance: ±1%; Power(Watts): 1/16W; Overload Voltage (Max): 50V; Temperature Coefficient: ±100ppm/℃
U1 = TPS5430DDAR: Manufacturer: TI(德州仪器); Add into BOM: yes; Function: 降压型; Output Type: 可调; Input Voltage: 5.5V~36V; Output Voltage: 1.221V~32.04V; Output Current: 3A; Switching Frequency: 500kHz; Synchronous Rectification: 否; Number of Outputs: 1; Topology: 降压式; Switch tube (built-in/external): 内置
U2 = MT3608L: Manufacturer: 西安航天民芯; Add into BOM: yes; Input Voltage: 2.2V~16V; Output Current: 2.5A; Number of Outputs: 1
U3 U4 = FD6288T: Manufacturer: Fortior Tech(峰岹); Symbol: FD6288; Add into BOM: yes
U5-U10 = TP181A1-CR: Manufacturer: 3PEAK(思瑞浦); Add into BOM: yes
U11 U12 = KH-2.54PH-1X3P-L13.5-WT: Manufacturer: kinghelm(金航标); Add into BOM: yes; Pin Structure: 1x3P; Pitch: 2.54mm
U13 U14 = MR30PW-M30.G.Y: Manufacturer: AMASS(艾迈斯); Add into BOM: yes
U15 = TPAL0220F10R0K9: Manufacturer: RESI(开步睿思); Add into BOM: yes; Tolerance: ±1%; Power(Watts): 35W; Temperature Coefficient: ±100ppm/℃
